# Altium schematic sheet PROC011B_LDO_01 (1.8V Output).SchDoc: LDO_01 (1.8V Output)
size 431 x 279 mm; Date: Not shown in title block; ApprovedBy: Not shown in title block; CheckedBy: Not shown in title block; Author: Not shown in title block; CompanyName: Not shown in title block; Engineer: Not shown in title block; Organization: Not shown in title block; Address1: Not shown in title block; Address2: Not shown in title block; Address3: Not shown in title block; Address4: Not shown in title block; DocumentNumber: 1; Revision: Use project parameter SCH_Rev; SheetNumber: 4; SheetTotal: 17; PageSetup: Record=PageOptions¦CenterHorizontal=True¦CenterVertical=True¦PrintScale=1.00¦XCorrection=1.00¦YCorrection=1.00¦PrintKind=0¦BorderSize=5000000¦LeftOffset=0¦BottomOffset=0¦Orientation=2¦PaperLength=1000¦PaperWidth=1000¦Scale=100¦PaperSource=15¦PrintQuality=600¦MediaType=1¦DitherType=10¦PaperKind=Letter¦PrintScaleMode=1
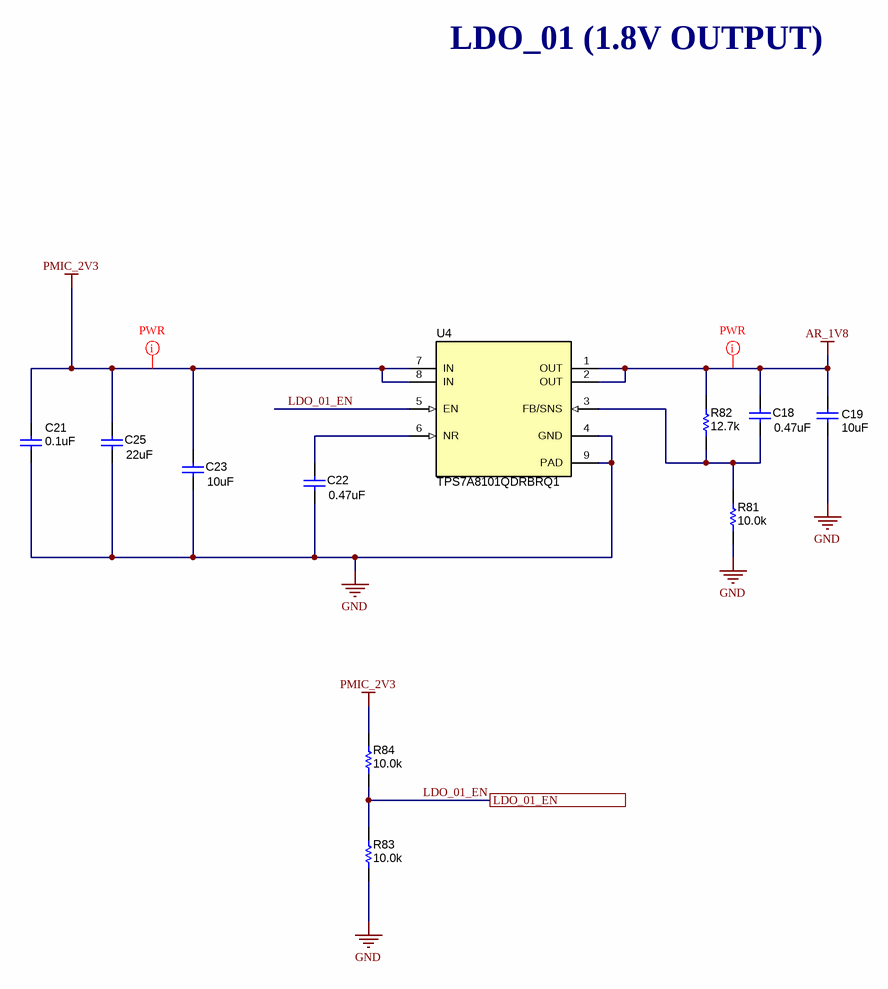
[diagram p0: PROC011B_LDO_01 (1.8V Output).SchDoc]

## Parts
C18  ValueDisplayed: 0.47uF  [0603]  (hidden comment: GCM188R71C474KA55D)
C19  ValueDisplayed: 10uF  [0805_HV]  (hidden comment: GCM21BR71A106KE22L)
C21  ValueDisplayed: 0.1uF  [0402L]  (hidden comment: CGA2B3X7R1H104K050BB)
C22  ValueDisplayed: 0.47uF  [0603]  (hidden comment: GCM188R71C474KA55D)
C23  ValueDisplayed: 10uF  [0805_HV]  (hidden comment: GCM21BR71A106KE22L)
C25  ValueDisplayed: 22uF  [1206_180]  (hidden comment: CGA5L1X7R0J226M160AC)
R81  ValueDisplayed: 10.0k  [0402L]  (hidden comment: CRCW040210K0FKED)
R82  ValueDisplayed: 12.7k  [0402L]  (hidden comment: CRCW040212K7FKED)
R83  ValueDisplayed: 10.0k  [0402L]  (hidden comment: CRCW040210K0FKED)
R84  ValueDisplayed: 10.0k  [0402L]  (hidden comment: CRCW040210K0FKED)
U4  TPS7A8101QDRBRQ1  [DRB0008A]

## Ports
LDO_01_EN

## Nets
AR_1V8: C18.2 C19.2 R82.2 U4.1(OUT) U4.2(OUT)
GND: C19.1 C21.1 C22.1 C23.1 C25.1 R81.1 R83.2 U4.4(GND) U4.9(PAD)
PMIC_2V3: C21.2 C23.2 C25.2 R84.1 U4.7(IN) U4.8(IN)
LDO_01_EN: R83.1 R84.2 U4.5(EN) ; port LDO_01_EN
NetC18_1: C18.1 R81.2 R82.1 U4.3(FB/SNS)
NetC22_2: C22.2 U4.6(NR)

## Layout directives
net class PWR: AR_1V8, PMIC_2V3

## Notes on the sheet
- LDO_01 (1.8V OUTPUT)

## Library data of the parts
C18 C22 = CMP-0007138-4: CAP, CERM, 0.47 uF, 16 V, +/- 10%, X7R, AEC-Q200 Grade 1, 0603; Manufacturer: MuRata; TaMin_C: -55°C; Polarized: N; SizeAreaWB_mm2: 4.68; Value1: Unknown; U/M: EA; Value: 0.47uF; TaMax_C: 125°C; SizeZ_mm: 1; SizeX_mm: 1.6; SizeY_mm: 0.8; Value2: 16V; SizeArea_mm2: 1.28; AEC Qualified: Y; Cap_F: 470nF; AEC Category: Q200
C19 C23 = CMP-0008017-2: CAP, CERM, 10 uF, 10 V, +/- 10%, X7R, 0805; Manufacturer: MuRata; TaMin_C: -55°C; Polarized: N; SizeAreaWB_mm2: 6.75; Value1: Unknown; U/M: EA; Value: 10uF; TaMax_C: 125°C; SizeZ_mm: 1.45; SizeX_mm: 2; SizeY_mm: 1.25; Cap_Case: 0805; Value2: 10V; SizeArea_mm2: 2.5; CompType: Capacitor; Cap_F: 10µF; AEC Category: Q200
C21 = CMP-0006325-2: CAP, CERM, 0.1 uF, 50 V, +/- 10%, X7R, AEC-Q200 Grade 1, 0402; Manufacturer: TDK; TaMin_C: -55°C; ESR_ohm: 0.039064; Polarized: N; SizeAreaWB_mm2: 3; Value1: 0.039064 ohm; U/M: EA; Value: 0.1uF; TaMax_C: 125°C; SizeZ_mm: 0.6; SizeX_mm: 1; SizeY_mm: 0.5; Cap_Case: 0402; Value2: 50V; AEC Qualified: Y; Cap_F: 100nF; IRMS_A: 8.14669dA; AEC Category: Q200
C25 = CMP-0008770-2: CAP, CERM, 22 uF, 6.3 V, +/- 10%, X7R, AEC-Q200 Grade 1, 1206; Manufacturer: TDK; TaMin_C: -55°C; ESR_ohm: 1.872m; Polarized: N; SizeAreaWB_mm2: 10.92; Value1: 0.001872 ohm; U/M: EA; Value: 22uF; SizeZ_mm: 1.8; SizeX_mm: 3.2; SizeY_mm: 1.6; Value2: 6.3V; SizeArea_mm2: 5.12; AEC Qualified: Y; Cap_F: 22µF; IRMS_A: 5.30203A; AEC Grade: 1; AEC Category: Q200; TaMax_C: 125°C
R81 R84 = CMP-0025958-2: RES, 10.0 k, 1%, 0.063 W, 0402; Manufacturer: Vishay-Dale; Power_W: 63mW; TempCo: 100 ppm/C; Value_Code: 10k0; U/M: EA; Value: 10.0k; EIA_Code: E96; Res_ohm: 10k; SizeX_mm: 1; SizeY_mm: 0.5; SizeZ_mm: 0.6; Value2: 0.063W; VDC_V: 50V; AEC Category: Q200
R82 = CMP-0025993-2: RES, 12.7 k, 1%, 0.063 W, 0402; Manufacturer: Vishay-Dale; Power_W: 63mW; TempCo: 100 ppm/C; Value_Code: 12k7; U/M: EA; Value: 12.7k; EIA_Code: E96; SizeX_mm: 1; SizeY_mm: 0.5; SizeZ_mm: 0.6; Value2: 0.063W; VDC_V: 50V; AEC Category: Q200
R83 = CMP-0025958-2: RES, 10.0 k, 1%, 0.063 W, 0402; Manufacturer: Vishay-Dale; Power_W: 63mW; TempCo: 100 ppm/C; Value_Code: 10k0; U/M: EA; Value: 10.0k; EIA_Code: E96; Res_ohm: 10k; SizeX_mm: 1; SizeY_mm: 0.5; SizeZ_mm: 0.6; Value2: 0.063W; CompType: Resistor; VDC_V: 50V; AEC Category: Q200; INSTALATION: DNP
U4 = CMP-0073870-2: Automotive Low-Noise, Wide-Bandwidth, High PSRR, Low-Dropout 1-A Linear Regulator, DRB0008A (VSON-8); Manufacturer: Texas Instruments; SizeZ_mm: 1.0; SizeX_mm: 3.0; SizeArea_mm2: 9.0; CompType: IC; U/M: EA; SizeAreaWB_mm2: 16.0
